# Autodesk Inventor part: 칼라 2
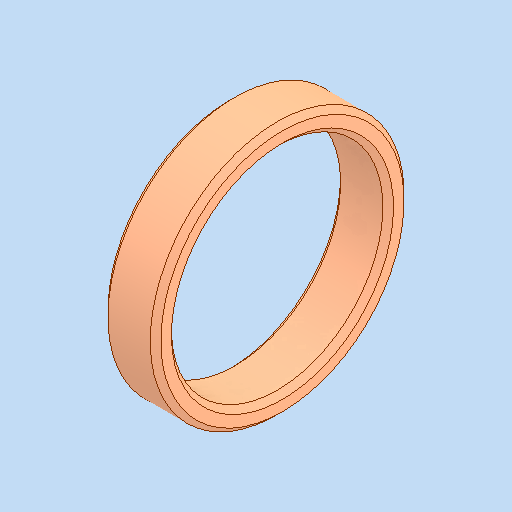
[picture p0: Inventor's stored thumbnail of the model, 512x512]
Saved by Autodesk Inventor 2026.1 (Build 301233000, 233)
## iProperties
Created: 2025-11
Part Number: 칼라 2
Material: 강철, 연강
Document SubType Name: Modeling
Designer: PC-30
Density: 7.85 g/cm^3
Appearance: 기본값
Author: jhkim
Sending System: Autodesk Inventor 2026
Preprocessor: ST-DEVELOPER v20.1
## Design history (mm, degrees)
feature "솔리드1"
node "솔리드2"
